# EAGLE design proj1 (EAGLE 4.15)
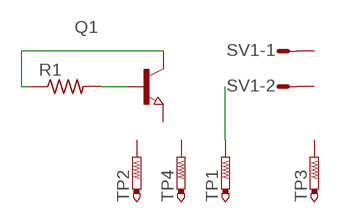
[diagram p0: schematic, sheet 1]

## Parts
Q1  NPN-TRANSISTOR_SOT23  [SOT23]
R1  R-US_M1206  [M1206]
SV1  L02P  [L02P]
TP1  P1-13  [P1-13]
TP2  P1-13Y  [P1-13Y]
TP3  P1-13  [P1-13]
TP4  P1-13Y  [P1-13Y]

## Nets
GND: TP1.1(PS)
N$4: Q1.3(C) R1.1
N$5: Q1.1(B) R1.2
Unconnected: Q1.2(E) SV1.1 SV1.2 TP2.1(PS) TP3.1(PS) TP4.1(PS)

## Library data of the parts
Q1 = semicon-smd-ipc:NPN-TRANSISTOR_: NPN TRANSISTOR
R1 = rcl:R-US_: RESISTOR, American symbol
SV1 = con-amp-mt:L02P: AMP MT CONNECTOR
TP1 TP3 = testpad:P1-13: TEST PIN
TP2 TP4 = testpad:P1-13Y: TEST PIN

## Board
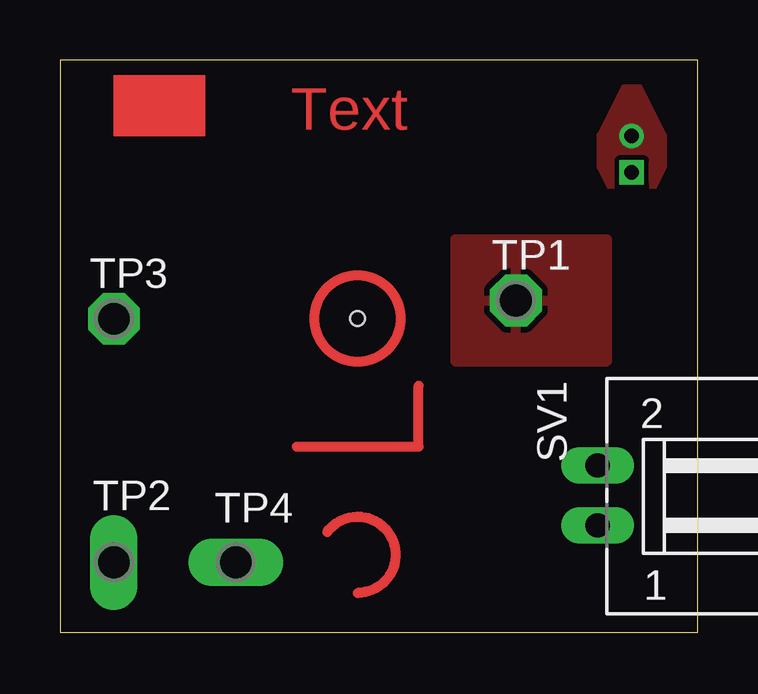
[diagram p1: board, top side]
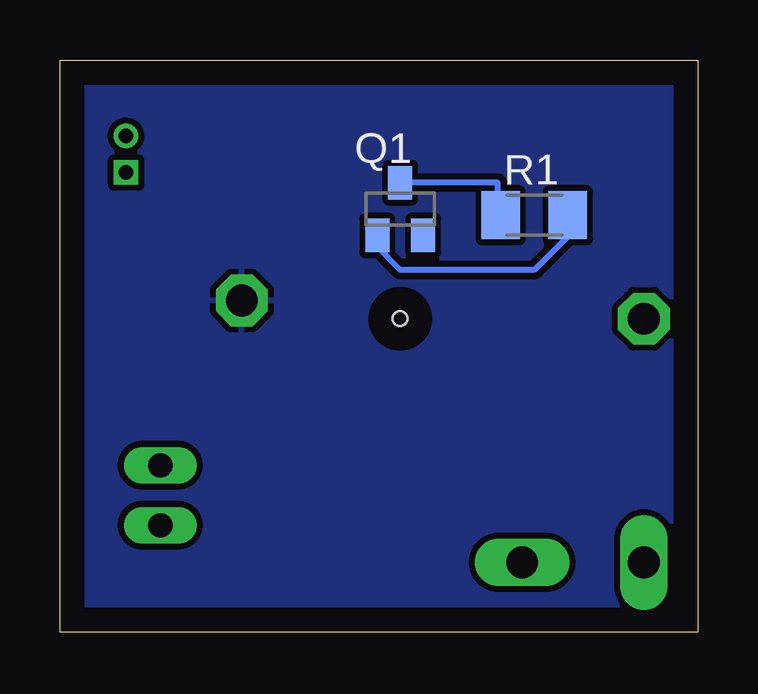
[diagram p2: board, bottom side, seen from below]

Size 26.59 x 23.87 mm. Coordinates in mm from the lower left corner, seen from the top.
Outline: 0,0 26.59,0 26.59,23.87 0,23.87 0,0
Copper layers (1*16): Top 0.035mm / dielectric 1.5mm / Bottom 0.035mm
Design rules "default": minimum track width 10mil, minimum drill 24mil, track to track 8mil, track to pad 8mil, pad to pad 8mil, via to via 8mil, smd to smd 8mil, copper to edge 40mil, drill to drill 8mil, minimum pad ring 10mil, minimum via ring 8mil, stop-mask expansion 4mil, vias tented up to drill 0mil, thermal gap 10mil
Holes 0.61 mm at 12.41,13.08

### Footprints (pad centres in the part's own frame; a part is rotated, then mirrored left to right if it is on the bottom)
SOT23 = smd 1 x 1.4: 1 -0.95,-1.1; 2 0.95,-1.1; 3 0,1.1
M1206 = smd 1.6 x 2: 1 -1.4,0; 2 1.4,0
L02P = drill 1.016 long: 1 1.25,-6.25; 2 -1.25,-6.25
P1-13 = drill 1.321 pad 2.159 octagon: 1 0,0
P1-13Y = drill 1.321 pad 1.905 long: 1 0,0

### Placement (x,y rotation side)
Q1  12.41,17.65 0 bottom
R1  6.82,17.39 0 bottom
SV1  28.66,5.71 270 top
TP1  19.01,13.84 0 top
TP2  2.25,2.92 0 top
TP3  2.25,13.08 0 top
TP4  7.33,2.92 90 top

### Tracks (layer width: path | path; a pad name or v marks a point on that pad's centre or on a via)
GND
  pour Bottom (isolate 0.254): 0.72,23.49 25.87,23.49 25.87,0.63 0.72,0.63
  pour Top: 16.47,16.38 16.47,11.3 22.82,11.3 22.82,16.38
N$1  (via drill 0.61)
  other vias: 23.84,20.7
  pour Top: 22.57,20.7 22.57,19.43 23.84,16.89 25.11,19.43 25.11,20.7 23.84,23.24
N$2
  Top 0.406: 9.87,7.74 14.95,7.74 14.95,10.28
N$3  (via drill 0.61)
  other vias: 23.84,19.17
N$4
  Bottom 0.254: R1.1 8.34,17.39 8.34,18.75 Q1.3
N$5
  Bottom 0.254: R1.2 5.42,16.51 6.82,15.11 12.41,15.11 13.42,16.12 13.36,16.19 Q1.1
S$1
  Top 0.406: 11.14,4.19 arc-233 12.41,1.65
(copper drawn outside any net)
  shapes: Top area x1, Top circle x1

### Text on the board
Top: Text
